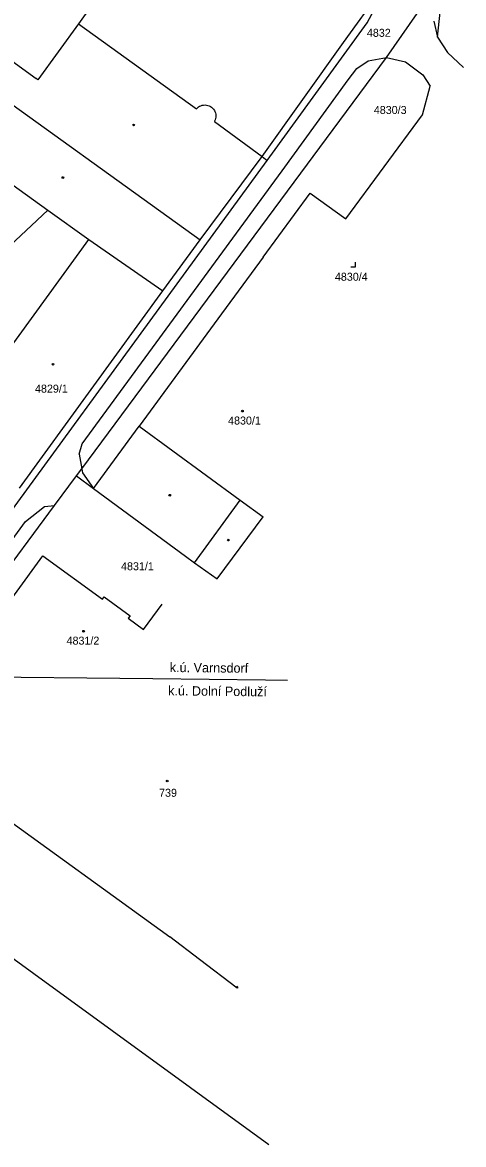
# Model space of a CAD drawing. Extents: x -717507 to -715515, y -957700 to -954941.
# Drawn here: x -716557.4 to -716463.7, y -956731 to -956492.7 of the extents above; entities that cross this region are included whole.
import ezdxf

# ---------------------------------------------------------------- set-up
doc = ezdxf.new("R2010")
doc.units = 0
for name, color, linetype in [('Hranice kat_území', 7, 'Continuous'), ('Hranice parcel', 7, 'Continuous'), ('Názevy ku_obce_kraje', 7, 'Continuous'), ('Parcelní čísla', 7, 'Continuous'), ('Vnitřní kresba', 7, 'Continuous'), ('Značky budov', 7, 'Continuous'), ('Značky kultur', 7, 'Continuous')]:
    doc.layers.add(name, color=color, linetype=linetype)

msp = doc.modelspace()

# ---------------------------------------------------------------- linework, layer by layer
at = {"layer": 'Hranice kat_území'}
for points in [[(-716571.72, -956631.58), (-716529.66, -956632.05)], [(-716529.66, -956632.05), (-716505.78, -956632.31)], [(-716505.78, -956632.31), (-716501.12, -956632.36)]]:
    msp.add_lwpolyline(points, dxfattribs=at)
at = {"layer": 'Hranice parcel'}
for points in [[(-716489.21, -956496.95), (-716481.19, -956485.79)], [(-716480.11, -956500.08), (-716470.33, -956486.04)], [(-716542.76, -956489.24), (-716545.44, -956492.93)], [(-716545.44, -956492.93), (-716520.44, -956511.02)], [(-716506.5, -956521.15), (-716489.21, -956496.95)], [(-716544.75, -956587.46), (-716480.11, -956500.08)], [(-716520.44, -956511.02), (-716520.23, -956510.81), (-716520, -956510.62), (-716519.75, -956510.47), (-716519.47, -956510.35), (-716519.19, -956510.26), (-716518.9, -956510.21), (-716518.6, -956510.2), (-716518.3, -956510.23), (-716518.01, -956510.29), (-716517.73, -956510.39), (-716517.47, -956510.52), (-716517.22, -956510.69), (-716517, -956510.88), (-716516.8, -956511.1), (-716516.63, -956511.35), (-716516.5, -956511.61), (-716516.4, -956511.89), (-716516.33, -956512.18), (-716516.31, -956512.48), (-716516.32, -956512.78), (-716516.36, -956513.07), (-716516.45, -956513.36), (-716516.57, -956513.63), (-716516.63, -956513.74)], [(-716488.69, -956534.4), (-716472.44, -956512.26)], [(-716516.63, -956513.74), (-716506.5, -956521.15)], [(-716583.26, -956628.67), (-716505.44, -956522.02)], [(-716506.5, -956521.15), (-716505.44, -956522.02)], [(-716564.19, -956523.78), (-716551.98, -956532.51)], [(-716506.3, -956542.56), (-716496.29, -956528.91)], [(-716496.29, -956528.91), (-716488.69, -956534.4)], [(-716561.15, -956541.15), (-716551.98, -956532.51)], [(-716506.3, -956542.56), (-716515.87, -956555.61)], [(-716515.87, -956555.61), (-716532.58, -956578.41)], [(-716542.27, -956591.67), (-716532.58, -956578.41)], [(-716550.56, -956595.31), (-716545.89, -956589)], [(-716545.89, -956589), (-716544.75, -956587.46)], [(-716545.89, -956589), (-716542.27, -956591.67)], [(-716542.27, -956591.67), (-716522.75, -956606.05)], [(-716577.35, -956631.52), (-716550.56, -956595.31)], [(-716516.03, -956610.87), (-716506.26, -956597.71)], [(-716571.72, -956631.58), (-716553, -956605.99)], [(-716553, -956605.99), (-716540.39, -956615.18)], [(-716522.75, -956606.05), (-716520.87, -956607.43)], [(-716520.87, -956607.43), (-716516.03, -956610.87)], [(-716540.39, -956615.18), (-716539.98, -956614.67)], [(-716539.98, -956614.67), (-716534.51, -956618.69)], [(-716531.67, -956621.6), (-716527.71, -956616.22)], [(-716534.51, -956618.69), (-716534.91, -956619.23)], [(-716534.91, -956619.23), (-716531.67, -956621.6)], [(-716564.29, -956659.3), (-716526.11, -956686.91)], [(-716571.67, -956682.62), (-716505.03, -956731.04)], [(-716519.77, -956691.7), (-716526.11, -956686.91)], [(-716511.78, -956697.8), (-716519.77, -956691.7)], [(-716511.87, -956697.42), (-716511.63, -956697.59)], [(-716511.63, -956697.59), (-716511.78, -956697.8)]]:
    msp.add_lwpolyline(points, dxfattribs=at)
at = {"layer": 'Vnitřní kresba'}
for points in [[(-716469.24, -956495.79), (-716467.83, -956482.47)], [(-716484.18, -956492.73), (-716481.64, -956487.98)], [(-716545.44, -956492.93), (-716554.06, -956504.86)], [(-716505.44, -956522.02), (-716484.18, -956492.73)], [(-716470.03, -956492.38), (-716469.24, -956495.79)], [(-716469.24, -956495.79), (-716467.11, -956499.07)], [(-716565.6, -956496.49), (-716554.42, -956504.6)], [(-716486.4, -956502.47), (-716484.01, -956500.8)], [(-716484.01, -956500.8), (-716480.11, -956500.08)], [(-716480.11, -956500.08), (-716476.08, -956501.01)], [(-716476.08, -956501.01), (-716472.4, -956503.78)], [(-716467.11, -956499.07), (-716463.74, -956502.22)], [(-716570.01, -956502.56), (-716519.63, -956538.84)], [(-716488.23, -956504.83), (-716486.4, -956502.47)], [(-716554.06, -956504.86), (-716554.42, -956504.6)], [(-716502.27, -956524.19), (-716488.23, -956504.83)], [(-716472.4, -956503.78), (-716470.79, -956506.23)], [(-716472.44, -956512.26), (-716470.79, -956506.23)], [(-716519.63, -956538.84), (-716506.5, -956521.15)], [(-716544.71, -956582.21), (-716502.27, -956524.19)], [(-716551.98, -956532.51), (-716543.28, -956538.76)], [(-716573.5, -956580.32), (-716543.28, -956538.76)], [(-716543.28, -956538.76), (-716527.56, -956549.69)], [(-716527.56, -956549.69), (-716519.63, -956538.84)], [(-716557.99, -956591.62), (-716527.56, -956549.69)], [(-716532.58, -956578.41), (-716511.12, -956594.15)], [(-716545.29, -956584.36), (-716544.71, -956582.21)], [(-716545.29, -956584.36), (-716544.75, -956587.46)], [(-716544.75, -956587.46), (-716544.59, -956588.36)], [(-716544.59, -956588.36), (-716542.27, -956591.67)], [(-716556.72, -956598.68), (-716552.71, -956595.47)], [(-716552.71, -956595.47), (-716550.56, -956595.31)], [(-716520.87, -956607.43), (-716511.12, -956594.15)], [(-716511.12, -956594.15), (-716506.26, -956597.71)], [(-716580.49, -956631.36), (-716556.72, -956598.68)]]:
    msp.add_lwpolyline(points, dxfattribs=at)
at = {"layer": 'Značky budov'}
for centre in [(-716533.77, -956514.45), (-716548.78, -956525.62), (-716550.87, -956565.27), (-716510.67, -956575.23), (-716526.09, -956593.1), (-716513.67, -956602.64), (-716544.39, -956621.99), (-716526.64, -956653.81)]:
    msp.add_circle(centre, 0.175, dxfattribs=at)
at = {"layer": 'Značky kultur'}
msp.add_lwpolyline([(-716487.69, -956544.58), (-716486.69, -956544.58), (-716486.69, -956543.58)], dxfattribs=at)

# ---------------------------------------------------------------- texts
at = {"layer": 'Názevy ku_obce_kraje'}
for s, rotation, p in [('k.ú. Varnsdorf', 359.3762, (-716526.1, -956630.65)), ('k.ú. Dolní Podluží', 359.3598, (-716526.45, -956635.6))]:
    msp.add_text(s, height=2, rotation=rotation, dxfattribs=at).set_placement(p)
at = {"layer": 'Parcelní čísla'}
for s, p in [('4832', (-716484.25, -956495.72)), ('4830/3', (-716482.78, -956512.11)), ('4830/4', (-716491.04, -956547.54)), ('4829/1', (-716554.69, -956571.31)), ('4830/1', (-716513.71, -956578.08)), ('4831/1', (-716536.43, -956609.04)), ('4831/2', (-716547.99, -956624.84)), ('739', (-716528.36, -956657.16))]:
    msp.add_text(s, height=1.7, dxfattribs=at).set_placement(p)

doc.saveas('drawing.dxf')
